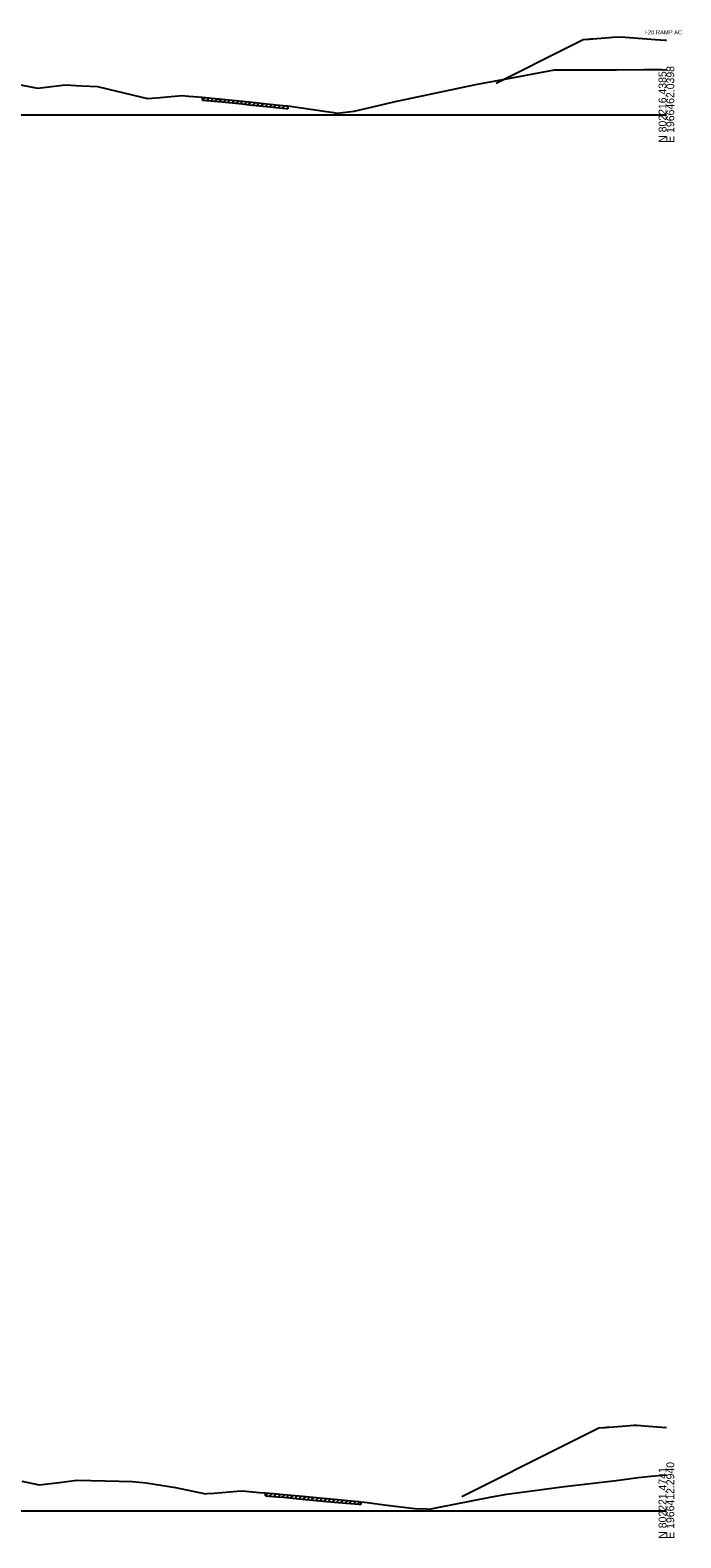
# Model space of a CAD drawing. Extents: x -26 to 1986619, y -10 to 827846.
# Drawn here: x 372 to 605, y 15990 to 16530 of the extents above; entities that cross this region are included whole.
import ezdxf

# ---------------------------------------------------------------- set-up
doc = ezdxf.new("R2010")
doc.units = 0
for name, color, linetype in [('RD_GPK_XS_Cell', 7, 'Continuous'), ('RD_TX_Misc1', 7, 'Continuous'), ('RD_XS_ExGround', 7, 'Continuous'), ('RD_XS_ExPaveRet', 7, 'Continuous'), ('RD_XS_Pave', 7, 'Continuous')]:
    doc.layers.add(name, color=color, linetype=linetype)

msp = doc.modelspace()

# ---------------------------------------------------------------- linework, layer by layer
at = {"layer": 'RD_GPK_XS_Cell'}
for p, q in [((300, 16500), (600, 16500)), ((300, 16000), (600, 16000))]:
    msp.add_line(p, q, dxfattribs=at)
at = {"layer": 'RD_XS_ExGround'}
for points in [[(367.03, 16511.1), (374.92, 16509.58), (377.05, 16509.83), (384.81, 16510.7), (390.7, 16510.42), (396.38, 16510.16), (412.2, 16506.33), (414.24, 16505.86), (418.74, 16506.26), (426.67, 16506.93), (429.05, 16506.73), (433.94, 16506.31), (439.55, 16505.77), (439.91, 16505.73), (440.99, 16505.62), (448.23, 16504.89), (450.75, 16504.63), (456.89, 16503.99), (462.72, 16503.38), (463.86, 16503.27), (464.49, 16503.18), (478.32, 16501.19), (481, 16500.81), (481.43, 16500.75), (482.09, 16500.62), (488.22, 16501.36), (497, 16503.35), (502.48, 16504.64), (531.16, 16510.77), (534.86, 16511.45), (542.18, 16512.79), (559.9, 16516.12), (582.09, 16516.17), (591.87, 16516.25), (594.72, 16516.23), (596.79, 16516.22), (598.41, 16516.19), (600, 16516.17)], [(369.26, 16010.6), (375.52, 16009.35), (382.76, 16010.19), (388.98, 16011), (404.05, 16010.57), (408.88, 16010.43), (413.79, 16009.98), (424.25, 16008.34), (434.97, 16006.1), (435.63, 16006.15), (438.1, 16006.34), (446.32, 16006.99), (448.3, 16007.15), (454.34, 16006.58), (456.48, 16006.41), (460.6, 16006.04), (462.97, 16005.83), (468.56, 16005.3), (475.88, 16004.61), (481.13, 16004.12), (488.41, 16003.47), (489.96, 16003.32), (490.61, 16003.25), (493.02, 16002.91), (498.91, 16002.13), (509.93, 16000.79), (514.29, 16000.64), (515.16, 16000.62), (517.5, 16001.07), (537.49, 16004.98), (542.9, 16005.98), (563.5, 16008.75), (582.06, 16010.9), (589.86, 16011.96), (594.45, 16012.44), (600, 16012.84)]]:
    msp.add_lwpolyline(points, dxfattribs=at)
at = {"layer": 'RD_XS_ExPaveRet'}
for p, q in [((433.94, 16505.31), (433.94, 16506.31)), ((433.94, 16505.31), (434.85, 16506.22)), ((433.94, 16505.31), (439.55, 16504.77)), ((435.44, 16505.16), (436.35, 16506.07)), ((436.94, 16505.02), (437.85, 16505.93)), ((438.44, 16504.87), (439.35, 16505.78)), ((439.55, 16504.77), (439.91, 16504.73)), ((439.91, 16504.73), (440.99, 16504.62)), ((439.94, 16504.73), (440.85, 16505.64)), ((440.99, 16504.62), (448.23, 16503.89)), ((441.44, 16504.58), (442.35, 16505.48)), ((442.94, 16504.42), (443.85, 16505.33)), ((444.44, 16504.27), (445.35, 16505.18)), ((445.94, 16504.12), (446.85, 16505.03)), ((447.44, 16503.97), (448.35, 16504.88)), ((448.23, 16503.89), (450.75, 16503.63)), ((448.94, 16503.82), (449.85, 16504.73)), ((450.44, 16503.67), (451.35, 16504.57)), ((450.75, 16503.63), (456.89, 16502.99)), ((451.94, 16503.51), (452.84, 16504.41)), ((453.44, 16503.35), (454.34, 16504.25)), ((454.94, 16503.19), (455.84, 16504.1)), ((456.44, 16503.03), (457.35, 16503.94)), ((457.94, 16502.88), (458.85, 16503.78)), ((459.44, 16502.72), (460.35, 16503.63)), ((460.94, 16502.56), (461.85, 16503.47)), ((462.44, 16502.41), (463.35, 16503.32)), ((456.89, 16502.99), (462.72, 16502.38)), ((462.72, 16502.38), (463.86, 16502.27)), ((463.86, 16502.27), (464.49, 16502.18)), ((464.49, 16503.18), (464.49, 16502.18)), ((456.48, 16005.41), (456.48, 16006.41)), ((456.48, 16005.41), (457.39, 16006.33)), ((456.48, 16005.41), (460.6, 16005.04)), ((457.98, 16005.28), (458.89, 16006.2)), ((459.48, 16005.14), (460.39, 16006.06)), ((460.6, 16005.04), (462.97, 16004.83)), ((460.98, 16005.01), (461.89, 16005.93)), ((462.48, 16004.87), (463.39, 16005.79)), ((462.97, 16004.83), (468.56, 16004.3)), ((463.98, 16004.73), (464.89, 16005.65)), ((465.48, 16004.59), (466.39, 16005.5)), ((466.98, 16004.45), (467.89, 16005.36)), ((468.48, 16004.3), (469.39, 16005.22)), ((468.56, 16004.3), (475.88, 16003.61)), ((469.98, 16004.16), (470.89, 16005.08)), ((471.48, 16004.02), (472.39, 16004.94)), ((472.98, 16003.88), (473.89, 16004.8)), ((474.48, 16003.74), (475.39, 16004.66)), ((475.88, 16003.61), (481.13, 16003.12)), ((475.98, 16003.6), (476.89, 16004.52)), ((477.48, 16003.46), (478.39, 16004.38)), ((478.98, 16003.32), (479.89, 16004.24)), ((480.48, 16003.18), (481.39, 16004.1)), ((481.13, 16003.12), (488.41, 16002.47)), ((481.98, 16003.04), (482.89, 16003.96)), ((483.48, 16002.91), (484.39, 16003.83)), ((484.98, 16002.78), (485.89, 16003.69)), ((486.48, 16002.64), (487.39, 16003.56)), ((487.98, 16002.51), (488.89, 16003.42)), ((488.41, 16002.47), (489.96, 16002.32)), ((489.48, 16002.36), (490.38, 16003.27)), ((489.96, 16002.32), (490.61, 16002.25)), ((490.61, 16003.25), (490.61, 16002.25))]:
    msp.add_line(p, q, dxfattribs=at)
at = {"layer": 'RD_XS_Pave'}
for points in [[(539.02, 16511.3), (565.93, 16524.85), (570.15, 16526.96), (571.82, 16527.1), (572.42, 16527.15), (572.91, 16527.19), (573.65, 16527.25), (578.12, 16527.63), (579.65, 16527.75), (580.67, 16527.79), (583.66, 16527.92), (596.07, 16527.01), (599.68, 16526.79), (600, 16526.78)], [(526.79, 16005.12), (563.15, 16023.33), (575.85, 16029.67), (577.46, 16029.8), (578.14, 16029.86), (578.64, 16029.9), (579.38, 16029.97), (581.14, 16030.11), (585.43, 16030.47), (588.38, 16030.61), (589.46, 16030.65), (593.61, 16030.34), (600, 16029.87)]]:
    msp.add_lwpolyline(points, dxfattribs=at)

# ---------------------------------------------------------------- texts
at = {"layer": 'RD_GPK_XS_Cell'}
for s, p in [('N 802216.4385', (600, 16490)), ('E 1966462.0398', (602.8, 16490)), ('E 1966412.2940', (602.8, 15990)), ('N 802221.4741', (600, 15990))]:
    msp.add_text(s, height=2.8, rotation=90, dxfattribs=at).set_placement(p)
at = {"layer": 'RD_TX_Misc1'}
msp.add_text('I-20 RAMP AC', height=1.5, dxfattribs=at).set_placement((592.09, 16528.81))

doc.saveas('drawing.dxf')
